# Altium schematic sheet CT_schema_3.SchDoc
size 334 x 183 mm
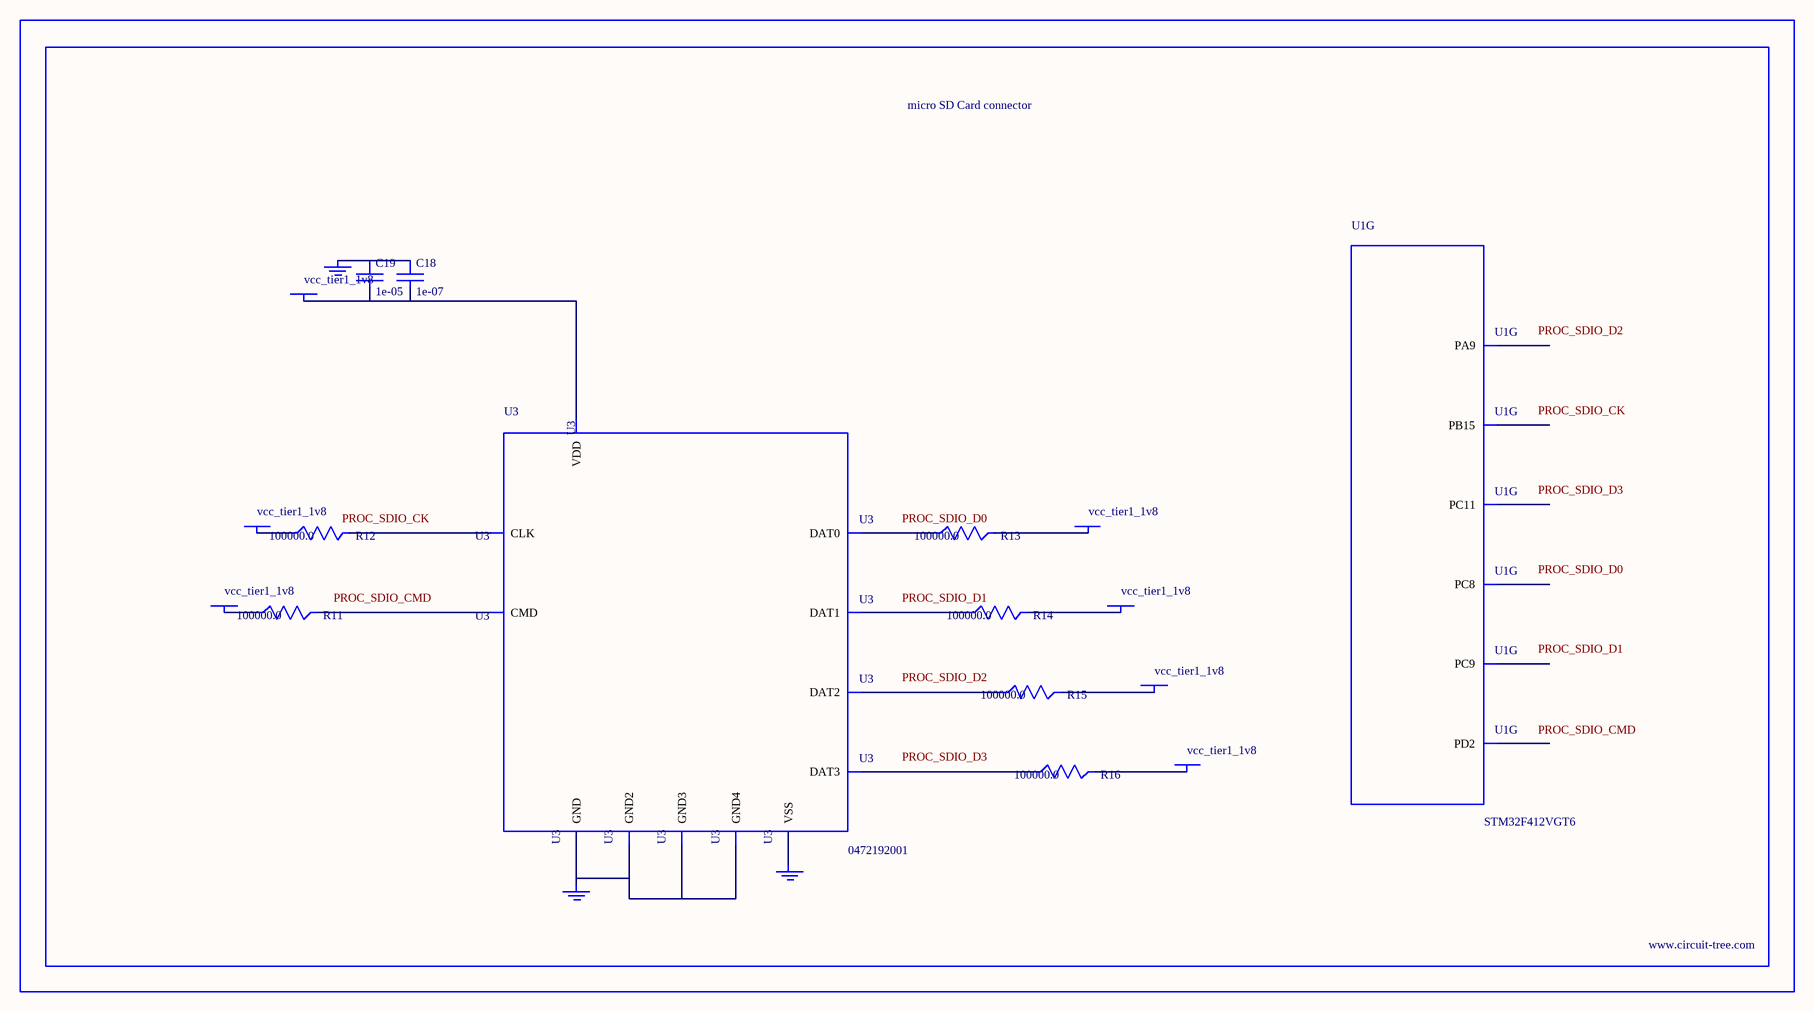
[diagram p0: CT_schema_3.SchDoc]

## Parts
BORDER2  (no value)
C18  1e-07  [C0402]
C19  1e-05  [C0805]
GND_INSTANCE_2_0  (no value)
GND_INSTANCE_2_1  (no value)
GND_INSTANCE_2_2  (no value)
POWER_INSTANCE_2_0  vcc_tier1_1v8
POWER_INSTANCE_2_1  vcc_tier1_1v8
POWER_INSTANCE_2_2  vcc_tier1_1v8
POWER_INSTANCE_2_3  vcc_tier1_1v8
POWER_INSTANCE_2_4  vcc_tier1_1v8
POWER_INSTANCE_2_5  vcc_tier1_1v8
POWER_INSTANCE_2_6  vcc_tier1_1v8
R11  100000.0  [R0603]
R12  100000.0  [R0603]
R13  100000.0  [R0603]
R14  100000.0  [R0603]
R15  100000.0  [R0603]
R16  100000.0  [R0603]
U1  STM32F412VGT6  [LQFP100]  (part G of 8)
U3  0472192001  [MOLEX_47219-2001]

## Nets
NetC18_1: C18.1 C19.1 GND_INSTANCE_2_0.0(GND)
NetC18_2: C18.2 C19.2 POWER_INSTANCE_2_3.0(PWR) U3.4(VDD)
NetGND_INSTANCE_2_1_0: GND_INSTANCE_2_1.0(GND) U3.6(VSS)
NetGND_INSTANCE_2_2_0: GND_INSTANCE_2_2.0(GND) U3.G1(GND) U3.G2(GND2) U3.G3(GND3) U3.G4(GND4)
NetPOWER_INSTANCE_2_0_0: POWER_INSTANCE_2_0.0(PWR) R15.2
NetPOWER_INSTANCE_2_1_0: POWER_INSTANCE_2_1.0(PWR) R16.2
NetPOWER_INSTANCE_2_2_0: POWER_INSTANCE_2_2.0(PWR) R11.1
NetPOWER_INSTANCE_2_4_0: POWER_INSTANCE_2_4.0(PWR) R12.1
NetPOWER_INSTANCE_2_5_0: POWER_INSTANCE_2_5.0(PWR) R13.2
NetPOWER_INSTANCE_2_6_0: POWER_INSTANCE_2_6.0(PWR) R14.2
NetR11_2: R11.2 U3.3(CMD)
NetR12_2: R12.2 U3.5(CLK)
NetR13_1: R13.1 U3.7(DAT0)
NetR14_1: R14.1 U3.8(DAT1)
NetR15_1: R15.1 U3.1(DAT2)
NetR16_1: R16.1 U3.2(DAT3)

Not connected (* = marked no-connect by the designer): U1 54(PB15) 65(PC8) 66(PC9) 68(PA9) 79(PC11) 83(PD2)

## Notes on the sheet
- Labels drawn without touching a wire or pin: PROC_SDIO_CK, PROC_SDIO_CMD, PROC_SDIO_D0, PROC_SDIO_D1, PROC_SDIO_D2, PROC_SDIO_D3

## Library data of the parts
BORDER2 = BORDER_PAGE2
C18 = C0402C104K3RACTU
C19 = C0805C106K8RACTU
GND_INSTANCE_2_0-GND_INSTANCE_2_2 = GND
POWER_INSTANCE_2_0-POWER_INSTANCE_2_6 = PWR
R11-R16 = RC0603JR-07100KL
